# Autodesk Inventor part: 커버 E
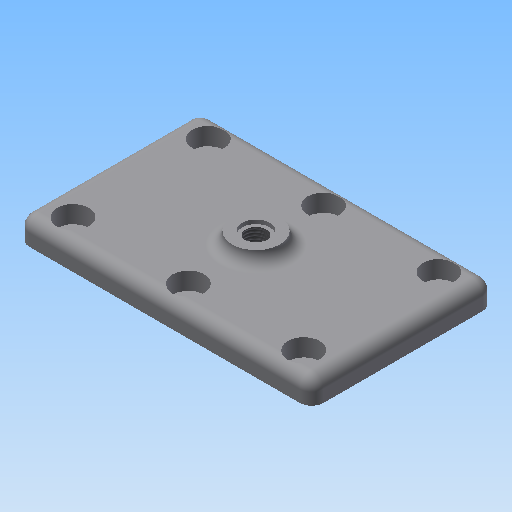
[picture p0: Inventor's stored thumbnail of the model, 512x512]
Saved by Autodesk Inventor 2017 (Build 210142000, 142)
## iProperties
Created: 2020-04
Part Number: 커버 E
Material: 알루미늄 6061
Document SubType Name: Modeling
Designer: mduedu
Density: 2.71 g/cm^3
Mass: 58.8274 g
Surface Area: 89.9592 cm^2
Volume: 21.7075 cm^3
Appearance: 기본값
Author: mduedu
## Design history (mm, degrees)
sketch "스케치1"
  geometry: L1 (37, 23)-(-37, 23); L2 (-37, 23)-(-37, -23); L3 (-37, -23)-(37, -23); L4 (37, -23)-(37, 23); L5 (37, 23)-(-37, -23); L6 (-37, 23)-(37, -23); 1 further point
  constraints: 12 end point, 2 midpoint, 2 parallel, 1 horizontal, 1 perpendicular
  dimensions: "d0" = 74 distance of L3.end L2.end; "d1" = 46 distance of L2.end L1.end
extrude "돌출1" new body sketch "스케치1" distance "d2" = 6; taper "d3" = 0 deg
sketch "스케치2"
  geometry: C1 r 6 at (0, 0); 1 further point
  constraints: 1 centre point, 1 coincident
  dimensions: "d4" = 12 diameter of C1
extrude "돌출2" join sketch "스케치2" distance "d5" = 3; taper "d6" = 0 deg
fillet "모깎기1" dims "d7" = 3
fillet "모깎기2" dims "d8" = 3
fillet "모깎기3" dims "d9" = 3
sketch "스케치3"
  geometry: L1 (-30, -13)-(30, -13); L2 (30, -13)-(30, 13); L3 (30, 13)-(-30, 13); L4 (-30, 13)-(-30, -13); L5 (-30, -13)-(30, 13); L6 (30, -13)-(-30, 13); 1 further point
  constraints: 12 end point, 2 midpoint, 2 parallel, 1 horizontal, 1 perpendicular
  dimensions: "d10" = 60 distance of L3.end L2.end; "d11" = 26 distance of L2.end L1.end
extrude "돌출3" join sketch "스케치3" distance "d12" = 2; taper "d13" = 0 deg
fillet "모깎기4" dims "d14" = 3
chamfer "모따기1" distance "d15" = 0.5; stored, may be unused: second distance "d16" = 2, angle "d17" = 45 deg
sketch "스케치4"
  geometry: L1 (-29, -17)-(29, -17); L2 (29, -17)-(29, 17); L3 (29, 17)-(-29, 17); L4 (-29, 17)-(-29, -17); L5 (-29, -17)-(29, 17); L6 (29, -17)-(-29, 17); 7 further points
  constraints: 12 end point, 4 coincident, 4 midpoint, 2 parallel, 1 horizontal, 1 perpendicular
  dimensions: "d18" = 58 distance of L3.end L2.end; "d19" = 34 distance of L2.end L1.end
hole "구멍1" sketch "스케치4" at (-29, 17), (-29, -17), (29, -17), (29, 17), (0, 17), (0, -17) diameter "d20" = 4.5; stored, may be unused: countersink angle "d24" = 90 deg, drill point angle "d26" = 118 deg; dims "d21" = 6, "d22" = 8, "d23" = 4.4, "d25" = 8
hole "구멍2" diameter "d29" = 5.188; stored, may be unused: countersink angle "d33" = 90 deg, drill point angle "d35" = 118 deg; dims "d27" = 10, "d28" = 10, "d30" = 6, "d31" = 8, "d32" = 4.4, "d34" = 8
sketch "스케치5"
  geometry: C1 r 3.5 at (0, 0); 1 further point
  constraints: 1 centre point, 1 coincident
  dimensions: "d36" = 7 diameter of C1
extrude "돌출4" cut sketch "스케치5" distance "d37" = 1; taper "d38" = 0 deg
node "솔리드1"
